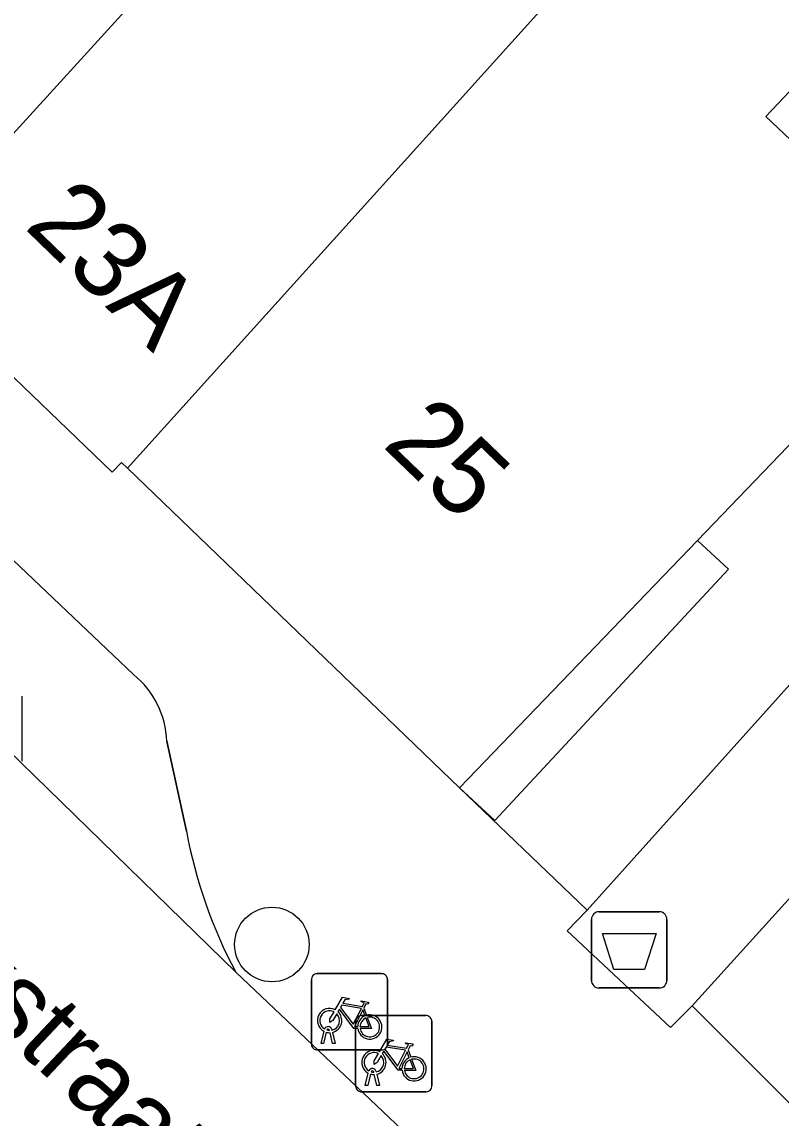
# Model space of a CAD drawing. Extents: x 160663 to 161506, y 382245 to 383291.
# Drawn here: x 160927.02 to 160936.98, y 383118.28 to 383132.65 of the extents above; entities that cross this region are included whole.
import ezdxf

# ---------------------------------------------------------------- set-up
doc = ezdxf.new("R2010")
doc.units = 0
for name, color, linetype in [('IMGEO_Afvalbak', 7, 'Continuous'), ('IMGEO_Boom', 7, 'Continuous'), ('IMGEO_Erf', 7, 'Continuous'), ('IMGEO_Fietsenrek', 7, 'Continuous'), ('IMGEO_Groenvoorziening', 7, 'Continuous'), ('IMGEO_Haag', 7, 'Continuous'), ('IMGEO_Kolk', 7, 'Continuous'), ('IMGEO_Openbare_ruimte_label', 7, 'Continuous'), ('IMGEO_Pand', 7, 'Continuous'), ('IMGEO_Pand_nummerreeks', 7, 'Continuous'), ('IMGEO_Parkeervlak_open', 7, 'Continuous'), ('IMGEO_Rijbaan_lokaal_open', 7, 'Continuous'), ('IMGEO_Voetpad_open', 7, 'Continuous')]:
    doc.layers.add(name, color=color, linetype=linetype)

msp = doc.modelspace()

# ---------------------------------------------------------------- linework, layer by layer
at = {"layer": 'IMGEO_Afvalbak'}
for p, q in [((160934.591, 383120.983), (160935.381, 383120.983)), ((160935.381, 383120.983), (160934.591, 383120.983)), ((160934.491, 383120.083), (160934.491, 383120.883)), ((160934.491, 383120.883), (160934.491, 383120.083)), ((160935.481, 383120.883), (160935.481, 383120.083)), ((160935.481, 383120.083), (160935.481, 383120.883)), ((160935.381, 383119.983), (160934.591, 383119.983)), ((160934.591, 383119.983), (160935.381, 383119.983))]:
    msp.add_line(p, q, dxfattribs=at)
msp.add_lwpolyline([(160934.634, 383120.697), (160935.338, 383120.697), (160935.189, 383120.227), (160934.783, 383120.227), (160934.634, 383120.697)], dxfattribs=at)
for centre, start, end in [((160934.591, 383120.883), 90, 180), ((160934.591, 383120.883), 90, 180), ((160935.381, 383120.883), 0, 90), ((160935.381, 383120.883), 360, 90), ((160934.591, 383120.083), 180, 270), ((160934.591, 383120.083), 180, 270), ((160935.381, 383120.083), 270, 0), ((160935.381, 383120.083), 270, 0)]:
    msp.add_arc(centre, 0.1, start, end, dxfattribs=at)
at = {"layer": 'IMGEO_Boom'}
msp.add_circle((160930.298, 383120.553), 0.489, dxfattribs=at)
at = {"layer": 'IMGEO_Erf'}
msp.add_lwpolyline([(160927.1, 383148.354), (160930.596, 383145.044), (160930.82, 383144.832), (160927.091, 383140.856), (160927.246, 383140.709), (160927.884, 383140.105), (160928.925, 383139.119), (160932.984, 383143.448), (160933.272, 383143.755), (160936.24, 383140.944), (160938.078, 383142.885), (160940.695, 383140.406), (160941.012, 383140.106), (160938.974, 383137.953), (160941.083, 383135.956), (160936.78, 383131.411), (160939.108, 383129.207), (160947.6, 383138.687), (160940.378, 383145.403), (160940.099, 383145.662)], dxfattribs=at)
at = {"layer": 'IMGEO_Fietsenrek'}
for p, q in [((160930.816, 383119.246), (160930.816, 383120.087)), ((160930.816, 383120.087), (160930.816, 383119.246)), ((160930.891, 383120.171), (160931.732, 383120.171)), ((160931.732, 383120.171), (160930.891, 383120.171)), ((160931.816, 383120.096), (160931.816, 383119.255)), ((160931.816, 383119.255), (160931.816, 383120.096)), ((160931.472, 383119.622), (160932.313, 383119.622)), ((160932.313, 383119.622), (160931.472, 383119.622)), ((160931.503, 383119.72), (160931.539, 383119.625)), ((160931.397, 383118.697), (160931.397, 383119.538)), ((160931.397, 383119.538), (160931.397, 383118.697)), ((160932.397, 383119.547), (160932.397, 383118.706)), ((160932.397, 383118.706), (160932.397, 383119.547)), ((160930.943, 383119.255), (160930.982, 383119.415)), ((160931.012, 383119.403), (160930.977, 383119.255)), ((160931.054, 383119.427), (160931.053, 383119.431)), ((160931.095, 383119.255), (160931.061, 383119.397)), ((160931.085, 383119.438), (160931.086, 383119.431)), ((160931.093, 383119.401), (160931.128, 383119.255)), ((160930.977, 383119.255), (160930.943, 383119.255)), ((160931.128, 383119.255), (160931.095, 383119.255)), ((160931.741, 383119.171), (160930.9, 383119.171)), ((160930.9, 383119.171), (160931.741, 383119.171)), ((160932.084, 383119.171), (160932.12, 383119.076)), ((160931.524, 383118.706), (160931.563, 383118.866)), ((160931.593, 383118.854), (160931.558, 383118.706)), ((160931.635, 383118.878), (160931.634, 383118.882)), ((160931.676, 383118.706), (160931.642, 383118.848)), ((160931.666, 383118.889), (160931.667, 383118.882)), ((160931.674, 383118.852), (160931.709, 383118.706)), ((160932.322, 383118.622), (160931.481, 383118.622)), ((160931.481, 383118.622), (160932.322, 383118.622)), ((160931.558, 383118.706), (160931.524, 383118.706)), ((160931.709, 383118.706), (160931.676, 383118.706))]:
    msp.add_line(p, q, dxfattribs=at)
for points in [[(160931.129, 383119.697), (160931.224, 383119.861), (160931.31, 383119.847), (160931.312, 383119.838), (160931.256, 383119.827), (160931.229, 383119.782), (160931.485, 383119.741)], [(160931.485, 383119.741), (160931.51, 383119.79), (160931.504, 383119.794), (160931.481, 383119.798), (160931.469, 383119.805), (160931.468, 383119.808), (160931.47, 383119.813), (160931.565, 383119.798), (160931.567, 383119.788), (160931.557, 383119.775), (160931.545, 383119.769), (160931.531, 383119.775), (160931.503, 383119.72)], [(160931.15, 383119.645), (160931.098, 383119.555), (160931.058, 383119.53), (160931.059, 383119.577), (160931.114, 383119.671)], [(160931.425, 383119.453), (160931.375, 383119.453), (160931.184, 383119.704), (160931.165, 383119.672)], [(160931.472, 383119.716), (160931.215, 383119.757), (160931.198, 383119.728), (160931.365, 383119.508), (160931.472, 383119.716)], [(160931.52, 383119.618), (160931.49, 383119.695), (160931.381, 383119.477), (160931.424, 383119.477)], [(160931.454, 383119.477), (160931.574, 383119.476), (160931.53, 383119.59)], [(160931.55, 383119.597), (160931.605, 383119.452), (160931.455, 383119.452)], [(160931.71, 383119.148), (160931.805, 383119.312), (160931.891, 383119.298), (160931.893, 383119.289), (160931.837, 383119.278), (160931.81, 383119.233), (160932.066, 383119.192)], [(160932.053, 383119.167), (160931.796, 383119.208), (160931.779, 383119.179), (160931.946, 383118.959), (160932.053, 383119.167)], [(160932.066, 383119.192), (160932.091, 383119.241), (160932.085, 383119.245), (160932.062, 383119.249), (160932.05, 383119.256), (160932.049, 383119.259), (160932.051, 383119.264), (160932.146, 383119.249), (160932.148, 383119.239), (160932.138, 383119.226), (160932.126, 383119.22), (160932.112, 383119.226), (160932.084, 383119.171)], [(160931.731, 383119.096), (160931.679, 383119.006), (160931.639, 383118.981), (160931.64, 383119.028), (160931.695, 383119.122)], [(160932.006, 383118.904), (160931.956, 383118.904), (160931.765, 383119.155), (160931.746, 383119.123)], [(160932.101, 383119.069), (160932.071, 383119.146), (160931.962, 383118.928), (160932.005, 383118.928)], [(160932.035, 383118.928), (160932.155, 383118.927), (160932.111, 383119.041)], [(160932.131, 383119.048), (160932.186, 383118.903), (160932.036, 383118.903)]]:
    msp.add_lwpolyline(points, dxfattribs=at)
for centre, radius, start, end in [((160930.894, 383120.093), 0.0779, 92.4484, 184.2845), ((160930.894, 383120.093), 0.0779, 92.4484, 184.2845), ((160931.738, 383120.093), 0.0779, 2.4484, 94.2845), ((160931.738, 383120.093), 0.0779, 2.4484, 94.2845), ((160931.056, 383119.556), 0.159, 62.6766, 242.1369), ((160931.056, 383119.556), 0.129, 63.3192, 238.903), ((160931.056, 383119.556), 0.129, 283.6043, 43.4302), ((160931.056, 383119.556), 0.159, 283.5766, 46.6042), ((160931.475, 383119.544), 0.0779, 92.4484, 184.2845), ((160931.475, 383119.544), 0.0779, 92.4484, 184.2845), ((160931.583, 383119.472), 0.159, 113.3408, 178.3217), ((160931.583, 383119.472), 0.159, 187.0065, 105.7708), ((160932.319, 383119.544), 0.0779, 2.4484, 94.2845), ((160932.319, 383119.544), 0.0779, 2.4484, 94.2845), ((160931.036, 383119.427), 0.0499, 12.8025, 158.6934), ((160931.583, 383119.472), 0.129, 113.923, 177.9556), ((160931.583, 383119.472), 0.129, 188.6715, 104.5883), ((160931.056, 383119.556), 0.159, 253.9967, 271.7867), ((160931.036, 383119.427), 0.0174, 12.8025, 163.4502), ((160931.056, 383119.556), 0.129, 253.415, 269.0204), ((160930.894, 383119.249), 0.0779, 182.4484, 274.2845), ((160930.894, 383119.249), 0.0779, 182.4484, 274.2845), ((160931.738, 383119.249), 0.0779, 272.4484, 4.2845), ((160931.738, 383119.249), 0.0779, 272.4484, 4.2845), ((160931.637, 383119.007), 0.159, 62.6766, 242.1369), ((160931.637, 383119.007), 0.129, 63.3192, 238.903), ((160931.637, 383119.007), 0.129, 283.6043, 43.4302), ((160931.637, 383119.007), 0.159, 283.5766, 46.6042), ((160932.164, 383118.923), 0.159, 113.3408, 178.3217), ((160932.164, 383118.923), 0.159, 187.0065, 105.7708), ((160932.164, 383118.923), 0.129, 113.923, 177.9556), ((160932.164, 383118.923), 0.129, 188.6715, 104.5883), ((160931.617, 383118.878), 0.0499, 12.8025, 158.6934), ((160931.637, 383119.007), 0.159, 253.9967, 271.7867), ((160931.617, 383118.878), 0.0174, 12.8025, 163.4502), ((160931.637, 383119.007), 0.129, 253.415, 269.0204), ((160931.475, 383118.7), 0.0779, 182.4484, 274.2845), ((160931.475, 383118.7), 0.0779, 182.4484, 274.2845), ((160932.319, 383118.7), 0.0779, 272.4484, 4.2845), ((160932.319, 383118.7), 0.0779, 272.4484, 4.2845)]:
    msp.add_arc(centre, radius, start, end, dxfattribs=at)
at = {"layer": 'IMGEO_Groenvoorziening'}
for points in [[(160932.761, 383122.608), (160933.222, 383122.179), (160936.288, 383125.473), (160935.881, 383125.852)], [(160934.171, 383120.731), (160935.53, 383119.466), (160935.811, 383119.75), (160938.919, 383123.174), (160937.558, 383124.478), (160934.436, 383121.004)]]:
    msp.add_lwpolyline(points, close=True, dxfattribs=at)
at = {"layer": 'IMGEO_Haag'}
msp.add_lwpolyline([(160932.761, 383122.608), (160933.222, 383122.179), (160936.288, 383125.473), (160935.881, 383125.852)], close=True, dxfattribs=at)
at = {"layer": 'IMGEO_Kolk'}
msp.add_line((160927.018, 383123.809), (160927.018, 383122.957), dxfattribs=at)
msp.add_lwpolyline([(160927.018, 383123.809), (160927.018, 383122.957)], dxfattribs=at)
at = {"layer": 'IMGEO_Pand'}
for points in [[(160936.24, 383140.944), (160933.272, 383143.755), (160932.984, 383143.448), (160928.925, 383139.119), (160927.884, 383140.105), (160927.246, 383140.709), (160927.091, 383140.856), (160920.779, 383134.126), (160920.856, 383134.043), (160925.467, 383129.608), (160931.721, 383136.471), (160931.871, 383136.329)], [(160938.65, 383138.154), (160940.695, 383140.406), (160938.078, 383142.885), (160936.24, 383140.944), (160931.871, 383136.329), (160931.721, 383136.471), (160925.467, 383129.608), (160925.4, 383129.44), (160928.203, 383126.744), (160928.327, 383126.872), (160928.405, 383126.797)], [(160928.405, 383126.797), (160932.761, 383122.608), (160935.881, 383125.852), (160939.108, 383129.207), (160936.78, 383131.411), (160941.083, 383135.956), (160938.974, 383137.953), (160941.012, 383140.106), (160940.695, 383140.406), (160938.65, 383138.154)]]:
    msp.add_lwpolyline(points, close=True, dxfattribs=at)
at = {"layer": 'IMGEO_Parkeervlak_open'}
for points in [[(160923.125, 383126.717), (160929.824, 383120.189)], [(160928.484, 383124.091), (160926.548, 383125.924)], [(160929.178, 383122.037), (160928.919, 383123.217)]]:
    msp.add_lwpolyline(points, dxfattribs=at)
for centre, radius, start, end in [((160927.738, 383123.175), 1.182, 2.0591, 50.861), ((160935.473, 383123.201), 6.402, 190.4731, 208.0628)]:
    msp.add_arc(centre, radius, start, end, dxfattribs=at)
at = {"layer": 'IMGEO_Rijbaan_lokaal_open'}
msp.add_lwpolyline([(160945.716, 383100.837), (160949.809, 383097.036), (160951.088, 383095.848), (160951.306, 383095.631), (160953.926, 383098.37), (160950.57, 383101.387), (160941.244, 383109.586), (160933.854, 383116.374), (160929.824, 383120.189), (160923.125, 383126.717), (160920.598, 383124.224), (160926.648, 383118.305), (160926.772, 383118.191), (160926.891, 383118.071), (160927.104, 383117.866), (160929.252, 383115.815), (160933.748, 383111.597), (160933.943, 383111.416)], dxfattribs=at)
at = {"layer": 'IMGEO_Voetpad_open'}
for points in [[(160954.192, 383098.131), (160961.813, 383091.279), (160964.067, 383093.823), (160956.981, 383100.29), (160952.66, 383104.233), (160948.39, 383108.129), (160948.102, 383108.392), (160948.002, 383108.283), (160942.448, 383113.457), (160937.416, 383118.145), (160935.811, 383119.75), (160935.53, 383119.466), (160934.171, 383120.731), (160934.436, 383121.004), (160932.761, 383122.608), (160928.405, 383126.797), (160928.327, 383126.872), (160928.203, 383126.744), (160925.4, 383129.44), (160925.467, 383129.608), (160920.856, 383134.043), (160920.779, 383134.126), (160920.569, 383134.352), (160914.367, 383141.037)], [(160939.108, 383129.207), (160935.881, 383125.852), (160936.288, 383125.473), (160933.222, 383122.179), (160932.761, 383122.608), (160934.436, 383121.004), (160937.558, 383124.478)], [(160926.548, 383125.924), (160928.484, 383124.091)], [(160928.919, 383123.217), (160929.178, 383122.037)], [(160938.919, 383123.174), (160935.811, 383119.75), (160937.416, 383118.145)], [(160929.824, 383120.189), (160933.854, 383116.374)]]:
    msp.add_lwpolyline(points, dxfattribs=at)
for centre, radius, start, end in [((160927.738, 383123.175), 1.182, 2.0591, 50.861), ((160935.473, 383123.201), 6.402, 190.4731, 208.0628)]:
    msp.add_arc(centre, radius, start, end, dxfattribs=at)

# ---------------------------------------------------------------- texts
at = {"layer": 'IMGEO_Openbare_ruimte_label'}
msp.add_text('Prins Hendrikstraat', height=1, rotation=316.662, dxfattribs=at).set_placement((160920.601, 383125.171))
at = {"layer": 'IMGEO_Pand_nummerreeks'}
for s, rotation, p in [('23A', 315.9166, (160927.036, 383129.953)), ('25', 316.1197, (160931.734, 383127.092))]:
    msp.add_text(s, height=1, rotation=rotation, dxfattribs=at).set_placement(p)

doc.saveas('drawing.dxf')
